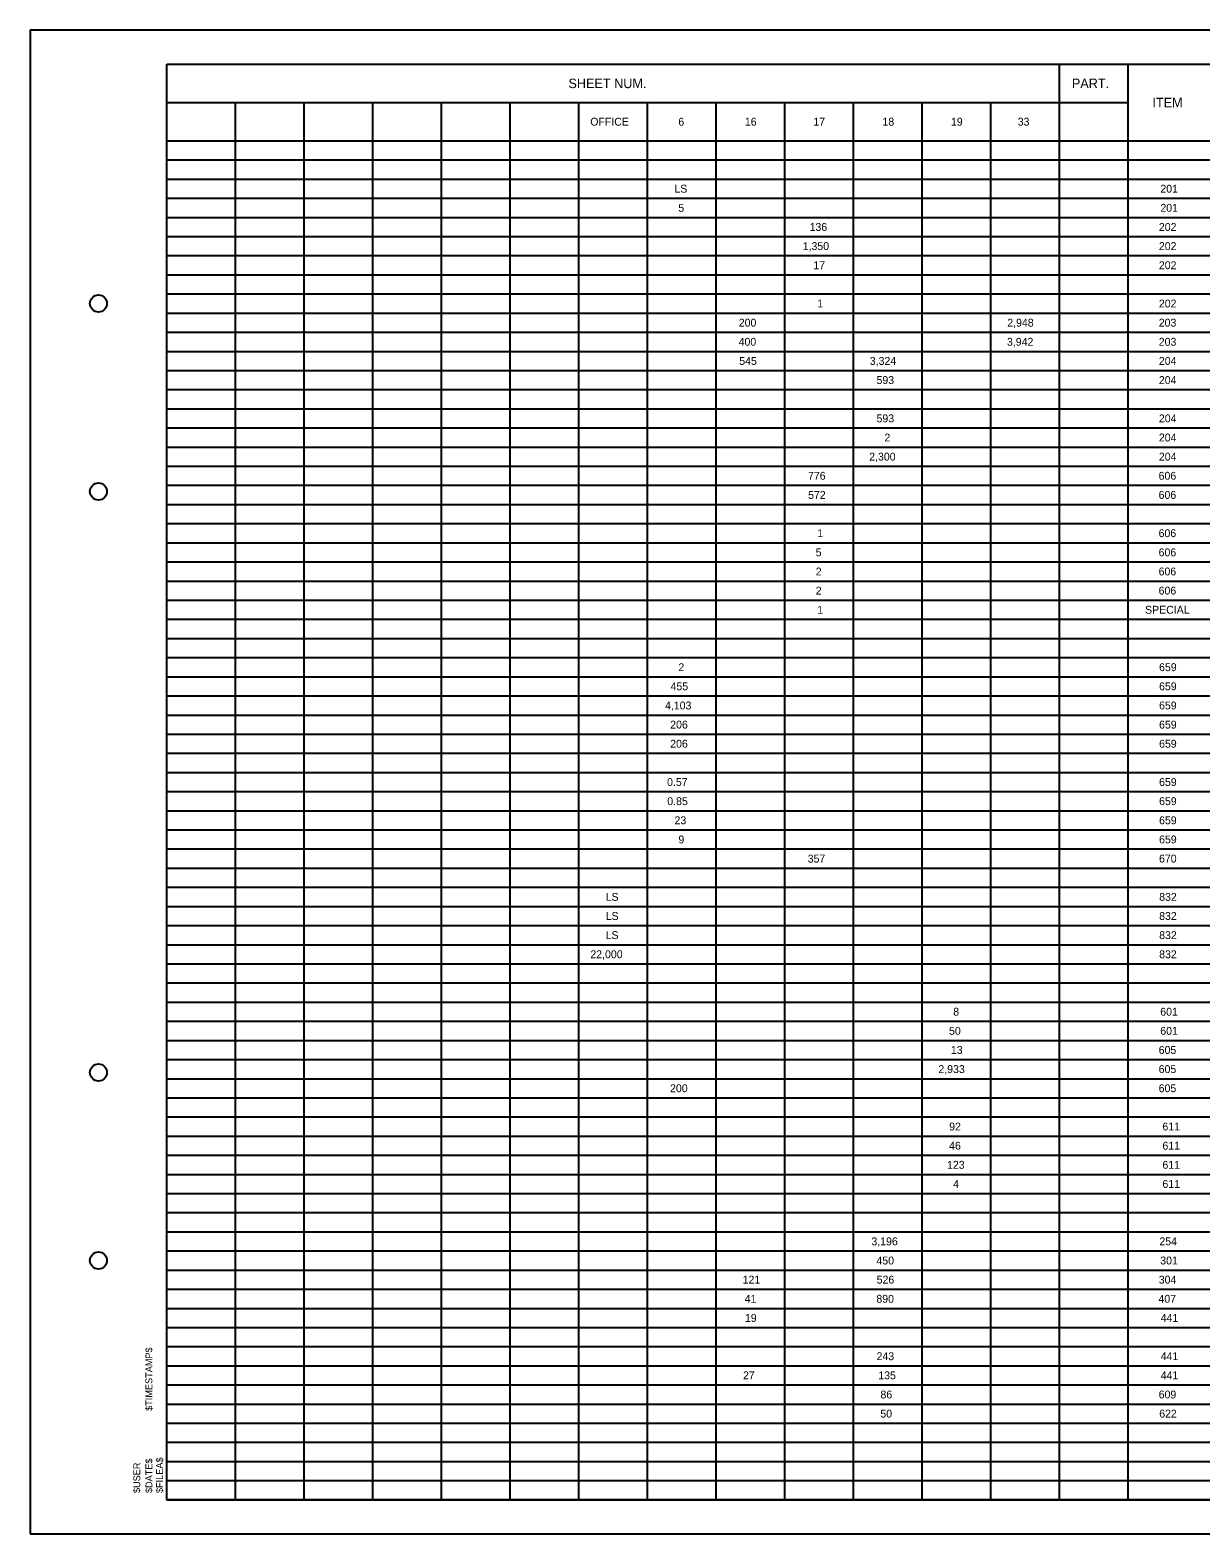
# Model space of a CAD drawing. Extents: x 0 to 34, y 0 to 22.
# Drawn here: x 0 to 17.13, y 0 to 22 of the extents above; entities that cross this region are included whole.
import ezdxf

# ---------------------------------------------------------------- set-up
doc = ezdxf.new("R2010")
doc.units = 0
for name, color, linetype in [('SH_Border', 7, 'Continuous'), ('SH_Cut_Line', 7, 'Continuous'), ('SH_Data', 7, 'Continuous'), ('SH_Text', 7, 'Continuous')]:
    doc.layers.add(name, color=color, linetype=linetype)

msp = doc.modelspace()

# ---------------------------------------------------------------- linework, layer by layer
at = {"layer": 'SH_Border'}
msp.add_lwpolyline([(2, 21.5), (33.5, 21.5), (33.5, 0.5), (2, 0.5)], close=True, dxfattribs=at)
for centre in [(1, 18), (1, 15.25), (1, 6.75), (1, 4)]:
    msp.add_circle(centre, 0.125, dxfattribs=at)
at = {"layer": 'SH_Cut_Line'}
msp.add_lwpolyline([(0, 0), (34, 0), (34, 22), (0, 22)], close=True, dxfattribs=at)
at = {"layer": 'SH_Text'}
for p, q in [((2, 21.5), (2, 21.5)), ((2, 21.5), (32.5, 21.5)), ((2, 0.5), (2, 21.5)), ((15.06, 0.5), (15.06, 21.5)), ((16.064, 0.5), (16.064, 21.5)), ((2, 20.94), (16.064, 20.94)), ((3.005, 0.5), (3.005, 20.94)), ((4.009, 0.5), (4.009, 20.94)), ((5.014, 0.5), (5.014, 20.94)), ((6.018, 0.5), (6.018, 20.94)), ((7.023, 0.5), (7.023, 20.94)), ((8.028, 0.5), (8.028, 20.94)), ((9.032, 0.5), (9.032, 20.94)), ((10.037, 0.5), (10.037, 20.94)), ((11.041, 0.5), (11.041, 20.94)), ((12.046, 0.5), (12.046, 20.94)), ((13.05, 0.5), (13.05, 20.94)), ((14.055, 0.5), (14.055, 20.94)), ((2, 20.38), (15.06, 20.38)), ((14.055, 20.38), (32.5, 20.38)), ((2, 20.1), (32.5, 20.1)), ((2, 19.82), (32.5, 19.82)), ((2, 19.54), (32.5, 19.54)), ((2, 19.26), (32.5, 19.26)), ((2, 18.98), (32.5, 18.98)), ((2, 18.7), (32.5, 18.7)), ((2, 18.42), (32.5, 18.42)), ((2, 18.14), (32.5, 18.14)), ((2, 17.86), (32.5, 17.86)), ((2, 17.58), (32.5, 17.58)), ((2, 17.3), (32.5, 17.3)), ((2, 17.02), (32.5, 17.02)), ((2, 16.74), (32.5, 16.74)), ((2, 16.46), (32.5, 16.46)), ((2, 16.18), (32.5, 16.18)), ((2, 15.9), (32.5, 15.9)), ((2, 15.62), (32.5, 15.62)), ((2, 15.34), (32.5, 15.34)), ((2, 15.06), (32.5, 15.06)), ((2, 14.78), (32.5, 14.78)), ((2, 14.5), (32.5, 14.5)), ((2, 14.22), (32.5, 14.22)), ((2, 13.94), (32.5, 13.94)), ((2, 13.66), (32.5, 13.66)), ((2, 13.38), (32.5, 13.38)), ((2, 13.1), (32.5, 13.1)), ((2, 12.82), (32.5, 12.82)), ((2, 12.54), (32.5, 12.54)), ((2, 12.26), (32.5, 12.26)), ((2, 11.98), (32.5, 11.98)), ((2, 11.7), (32.5, 11.7)), ((2, 11.42), (32.5, 11.42)), ((2, 11.14), (32.5, 11.14)), ((2, 10.86), (32.5, 10.86)), ((2, 10.58), (32.5, 10.58)), ((2, 10.3), (32.5, 10.3)), ((2, 10.02), (32.5, 10.02)), ((2, 9.74), (32.5, 9.74)), ((2, 9.46), (32.5, 9.46)), ((2, 9.18), (32.5, 9.18)), ((2, 8.9), (32.5, 8.9)), ((2, 8.62), (32.5, 8.62)), ((2, 8.34), (32.5, 8.34)), ((2, 8.06), (32.5, 8.06)), ((2, 7.78), (32.5, 7.78)), ((2, 7.5), (32.5, 7.5)), ((2, 7.22), (32.5, 7.22)), ((2, 6.94), (32.5, 6.94)), ((2, 6.66), (32.5, 6.66)), ((2, 6.38), (32.5, 6.38)), ((2, 6.1), (32.5, 6.1)), ((2, 5.82), (32.5, 5.82)), ((2, 5.54), (32.5, 5.54)), ((2, 5.26), (32.5, 5.26)), ((2, 4.98), (32.5, 4.98)), ((2, 4.7), (32.5, 4.7)), ((2, 4.42), (32.5, 4.42)), ((2, 4.14), (32.5, 4.14)), ((2, 3.86), (32.5, 3.86)), ((2, 3.58), (32.5, 3.58)), ((2, 3.3), (32.5, 3.3)), ((2, 3.02), (32.5, 3.02)), ((2, 2.74), (32.5, 2.74)), ((2, 2.46), (32.5, 2.46)), ((2, 2.18), (32.5, 2.18)), ((2, 1.9), (32.5, 1.9)), ((2, 1.62), (32.5, 1.62)), ((2, 1.34), (32.5, 1.34)), ((2, 1.06), (32.5, 1.06)), ((2, 0.78), (32.5, 0.78)), ((2, 0.5), (32.5, 0.5))]:
    msp.add_line(p, q, dxfattribs=at)

# ---------------------------------------------------------------- texts
at = {"layer": 'SH_Data'}
for s, p in [('$TIMESTAMP$', (1.788, 1.8)), ('$DATE$', (1.788, 0.598)), ('$FILEA$', (1.944, 0.598)), ('$USER', (1.611, 0.598))]:
    msp.add_text(s, height=0.1, rotation=89.9931, dxfattribs=at).set_placement(p)
at = {"layer": 'SH_Text'}
for s, height, p in [('SHEET NUM.', 0.1384, (7.876, 21.151)), ('PART.', 0.1384, (15.241, 21.151)), ('ITEM', 0.1384, (16.419, 20.871)), ('OFFICE', 0.1153, (8.195, 20.602)), ('6', 0.115, (9.484, 20.602)), ('16', 0.1153, (10.457, 20.602)), ('17', 0.1153, (11.459, 20.602)), ('18', 0.1153, (12.47, 20.602)), ('19', 0.1153, (13.472, 20.602)), ('33', 0.1153, (14.449, 20.602)), ('LS', 0.1153, (9.426, 19.622)), ('201', 0.1153, (16.536, 19.622)), ('5', 0.115, (9.484, 19.342)), ('201', 0.1153, (16.536, 19.342)), ('136', 0.1153, (11.404, 19.062)), ('202', 0.1153, (16.514, 19.062)), ('1,350', 0.1153, (11.303, 18.782)), ('202', 0.1153, (16.514, 18.782)), ('17', 0.1153, (11.459, 18.502)), ('202', 0.1153, (16.514, 18.502)), ('1', 0.115, (11.516, 17.942)), ('202', 0.1153, (16.514, 17.942)), ('200', 0.1153, (10.368, 17.662)), ('2,948', 0.1153, (14.296, 17.662)), ('203', 0.1153, (16.512, 17.662)), ('400', 0.1153, (10.366, 17.382)), ('3,942', 0.1153, (14.292, 17.382)), ('203', 0.1153, (16.512, 17.382)), ('545', 0.1153, (10.375, 17.102)), ('3,324', 0.1153, (12.285, 17.102)), ('204', 0.1153, (16.514, 17.102)), ('593', 0.1153, (12.383, 16.822)), ('204', 0.1153, (16.514, 16.822)), ('593', 0.1153, (12.383, 16.262)), ('204', 0.1153, (16.514, 16.262)), ('2', 0.115, (12.499, 15.982)), ('204', 0.1153, (16.514, 15.982)), ('2,300', 0.1153, (12.276, 15.702)), ('204', 0.1153, (16.514, 15.702)), ('776', 0.1153, (11.381, 15.422)), ('606', 0.1153, (16.51, 15.422)), ('572', 0.1153, (11.382, 15.142)), ('606', 0.1153, (16.51, 15.142)), ('1', 0.115, (11.516, 14.582)), ('606', 0.1153, (16.51, 14.582)), ('5', 0.115, (11.493, 14.302)), ('606', 0.1153, (16.51, 14.302)), ('2', 0.115, (11.494, 14.022)), ('606', 0.1153, (16.51, 14.022)), ('2', 0.115, (11.494, 13.742)), ('606', 0.1153, (16.51, 13.742)), ('1', 0.115, (11.516, 13.462)), ('SPECIAL', 0.1153, (16.312, 13.462)), ('2', 0.115, (9.485, 12.622)), ('659', 0.1153, (16.517, 12.622)), ('455', 0.1153, (9.37, 12.342)), ('659', 0.1153, (16.517, 12.342)), ('4,103', 0.1153, (9.289, 12.062)), ('659', 0.1153, (16.517, 12.062)), ('206', 0.1153, (9.365, 11.782)), ('659', 0.1153, (16.517, 11.782)), ('206', 0.1153, (9.365, 11.502)), ('659', 0.1153, (16.517, 11.502)), ('0.57', 0.1153, (9.319, 10.942)), ('659', 0.1153, (16.517, 10.942)), ('0.85', 0.1153, (9.322, 10.662)), ('659', 0.1153, (16.517, 10.662)), ('23', 0.1153, (9.428, 10.382)), ('659', 0.1153, (16.517, 10.382)), ('9', 0.115, (9.485, 10.102)), ('659', 0.1153, (16.517, 10.102)), ('357', 0.1153, (11.376, 9.822)), ('670', 0.1153, (16.516, 9.822)), ('LS', 0.1153, (8.421, 9.262)), ('832', 0.1153, (16.518, 9.262)), ('LS', 0.1153, (8.421, 8.982)), ('832', 0.1153, (16.518, 8.982)), ('LS', 0.1153, (8.421, 8.702)), ('832', 0.1153, (16.518, 8.702)), ('22,000', 0.1153, (8.197, 8.422)), ('832', 0.1153, (16.518, 8.422)), ('8', 0.115, (13.505, 7.582)), ('601', 0.1153, (16.534, 7.582)), ('50', 0.1153, (13.444, 7.302)), ('601', 0.1153, (16.534, 7.302)), ('13', 0.1153, (13.471, 7.022)), ('605', 0.1153, (16.511, 7.022)), ('2,933', 0.1153, (13.288, 6.742)), ('605', 0.1153, (16.511, 6.742)), ('200', 0.1153, (9.363, 6.462)), ('605', 0.1153, (16.511, 6.462)), ('92', 0.1153, (13.446, 5.902)), ('611', 0.1153, (16.566, 5.902)), ('46', 0.1153, (13.445, 5.622)), ('611', 0.1153, (16.566, 5.622)), ('123', 0.1153, (13.415, 5.342)), ('611', 0.1153, (16.566, 5.342)), ('4', 0.115, (13.504, 5.062)), ('611', 0.1153, (16.566, 5.062)), ('3,196', 0.1153, (12.308, 4.222)), ('254', 0.1153, (16.521, 4.222)), ('450', 0.1153, (12.382, 3.942)), ('301', 0.1153, (16.534, 3.942)), ('121', 0.1153, (10.425, 3.662)), ('526', 0.1153, (12.385, 3.662)), ('304', 0.1153, (16.512, 3.662)), ('41', 0.1153, (10.454, 3.382)), ('890', 0.1153, (12.381, 3.382)), ('407', 0.1153, (16.508, 3.382)), ('19', 0.1153, (10.458, 3.102)), ('441', 0.1153, (16.54, 3.102)), ('243', 0.1153, (12.384, 2.542)), ('441', 0.1153, (16.54, 2.542)), ('27', 0.1153, (10.43, 2.262)), ('135', 0.1153, (12.409, 2.262)), ('441', 0.1153, (16.54, 2.262)), ('86', 0.1153, (12.441, 1.982)), ('609', 0.1153, (16.511, 1.982)), ('50', 0.1153, (12.439, 1.702)), ('622', 0.1153, (16.519, 1.702))]:
    msp.add_text(s, height=height, dxfattribs=at).set_placement(p)

doc.saveas('drawing.dxf')
